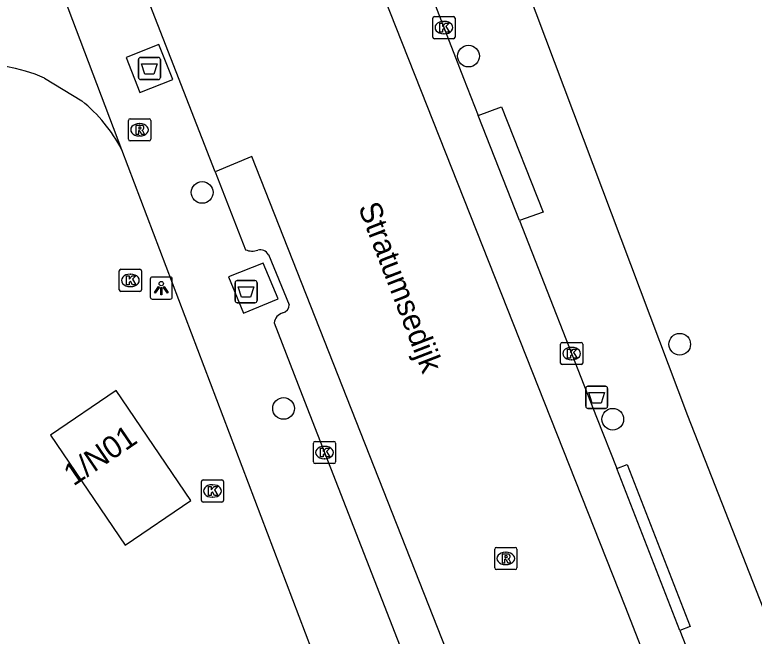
# Model space of a CAD drawing. Extents: x 161087 to 161922, y 382574 to 383873.
# Drawn here: x 161740.93 to 161774.27, y 382676.22 to 382704.24 of the extents above; entities that cross this region are included whole.
import ezdxf

# ---------------------------------------------------------------- set-up
doc = ezdxf.new("R2010")
doc.units = 0
for name, color, linetype in [('IMGEO_Afval_apart_plaats', 7, 'Continuous'), ('IMGEO_Afvalbak', 7, 'Continuous'), ('IMGEO_Boom', 7, 'Continuous'), ('IMGEO_Kolk', 7, 'Continuous'), ('IMGEO_Lichtpunt', 7, 'Continuous'), ('IMGEO_Openbare_ruimte_label', 7, 'Continuous'), ('IMGEO_Pand', 7, 'Continuous'), ('IMGEO_Pand_nummerreeks', 7, 'Continuous'), ('IMGEO_Rijbaan_lokaal_open', 7, 'Continuous'), ('IMGEO_Rioolput', 7, 'Continuous'), ('IMGEO_Voetpad_gesloten', 7, 'Continuous'), ('IMGEO_Voetpad_open', 7, 'Continuous')]:
    doc.layers.add(name, color=color, linetype=linetype)

msp = doc.modelspace()

# ---------------------------------------------------------------- linework, layer by layer
at = {"layer": 'IMGEO_Afval_apart_plaats'}
for p, q in [((161746.509, 382701.417), (161746.509, 382702.217)), ((161746.509, 382702.217), (161746.509, 382701.417)), ((161746.609, 382702.317), (161747.399, 382702.317)), ((161747.399, 382702.317), (161746.609, 382702.317)), ((161747.499, 382702.217), (161747.499, 382701.417)), ((161747.499, 382701.417), (161747.499, 382702.217)), ((161747.399, 382701.317), (161746.609, 382701.317)), ((161746.609, 382701.317), (161747.399, 382701.317)), ((161750.867, 382691.355), (161750.867, 382692.155)), ((161750.867, 382692.155), (161750.867, 382691.355)), ((161750.967, 382692.255), (161751.757, 382692.255)), ((161751.757, 382692.255), (161750.967, 382692.255)), ((161751.857, 382692.155), (161751.857, 382691.355)), ((161751.857, 382691.355), (161751.857, 382692.155)), ((161751.757, 382691.255), (161750.967, 382691.255)), ((161750.967, 382691.255), (161751.757, 382691.255))]:
    msp.add_line(p, q, dxfattribs=at)
for points in [[(161746.652, 382702.031), (161747.356, 382702.031), (161747.207, 382701.561), (161746.801, 382701.561), (161746.652, 382702.031)], [(161751.01, 382691.969), (161751.714, 382691.969), (161751.565, 382691.499), (161751.159, 382691.499), (161751.01, 382691.969)]]:
    msp.add_lwpolyline(points, dxfattribs=at)
for centre, start, end in [((161746.609, 382702.217), 90, 180), ((161746.609, 382702.217), 90, 180), ((161747.399, 382702.217), 0, 90), ((161747.399, 382702.217), 360, 90), ((161746.609, 382701.417), 180, 270), ((161746.609, 382701.417), 180, 270), ((161747.399, 382701.417), 270, 0), ((161747.399, 382701.417), 270, 0), ((161750.967, 382692.155), 90, 180), ((161750.967, 382692.155), 90, 180), ((161751.757, 382692.155), 0, 90), ((161751.757, 382692.155), 360, 90), ((161750.967, 382691.355), 180, 270), ((161750.967, 382691.355), 180, 270), ((161751.757, 382691.355), 270, 0), ((161751.757, 382691.355), 270, 0)]:
    msp.add_arc(centre, 0.1, start, end, dxfattribs=at)
at = {"layer": 'IMGEO_Afvalbak'}
for p, q in [((161766.676, 382686.587), (161766.676, 382687.387)), ((161766.676, 382687.387), (161766.676, 382686.587)), ((161766.776, 382687.487), (161767.566, 382687.487)), ((161767.566, 382687.487), (161766.776, 382687.487)), ((161767.666, 382687.387), (161767.666, 382686.587)), ((161767.666, 382686.587), (161767.666, 382687.387)), ((161767.566, 382686.487), (161766.776, 382686.487)), ((161766.776, 382686.487), (161767.566, 382686.487))]:
    msp.add_line(p, q, dxfattribs=at)
msp.add_lwpolyline([(161766.819, 382687.201), (161767.523, 382687.201), (161767.374, 382686.731), (161766.968, 382686.731), (161766.819, 382687.201)], dxfattribs=at)
for centre, start, end in [((161766.776, 382687.387), 90, 180), ((161766.776, 382687.387), 90, 180), ((161767.566, 382687.387), 0, 90), ((161767.566, 382687.387), 360, 90), ((161766.776, 382686.587), 180, 270), ((161766.776, 382686.587), 180, 270), ((161767.566, 382686.587), 270, 0), ((161767.566, 382686.587), 270, 0)]:
    msp.add_arc(centre, 0.1, start, end, dxfattribs=at)
at = {"layer": 'IMGEO_Boom'}
for centre in [(161761.392, 382702.376), (161749.383, 382696.228), (161770.915, 382689.383), (161753.053, 382686.487), (161767.897, 382686)]:
    msp.add_circle(centre, 0.489, dxfattribs=at)
at = {"layer": 'IMGEO_Kolk'}
for p, q in [((161759.783, 382703.234), (161759.783, 382704.086)), ((161759.858, 382704.16), (161760.71, 382704.16)), ((161760.784, 382704.086), (161760.784, 382703.234)), ((161760.271, 382703.94), (161760.296, 382703.94)), ((161760.294, 382703.38), (161760.269, 382703.38)), ((161760.71, 382703.16), (161759.858, 382703.16)), ((161745.647, 382691.837), (161745.647, 382692.689)), ((161745.722, 382692.763), (161746.574, 382692.763)), ((161746.648, 382692.689), (161746.648, 382691.837)), ((161746.135, 382692.543), (161746.16, 382692.543)), ((161746.574, 382691.763), (161745.722, 382691.763)), ((161746.158, 382691.983), (161746.133, 382691.983)), ((161765.541, 382688.536), (161765.541, 382689.388)), ((161765.616, 382689.462), (161766.468, 382689.462)), ((161766.542, 382689.388), (161766.542, 382688.536)), ((161766.029, 382689.242), (161766.054, 382689.242)), ((161766.468, 382688.462), (161765.616, 382688.462)), ((161766.052, 382688.682), (161766.027, 382688.682)), ((161754.397, 382684.073), (161754.397, 382684.925)), ((161754.472, 382684.999), (161755.324, 382684.999)), ((161754.885, 382684.779), (161754.91, 382684.779)), ((161755.398, 382684.925), (161755.398, 382684.073)), ((161754.908, 382684.219), (161754.883, 382684.219)), ((161755.324, 382683.999), (161754.472, 382683.999)), ((161749.348, 382682.339), (161749.348, 382683.191)), ((161749.423, 382683.265), (161750.275, 382683.265)), ((161749.836, 382683.045), (161749.861, 382683.045)), ((161750.349, 382683.191), (161750.349, 382682.339)), ((161749.859, 382682.485), (161749.834, 382682.485)), ((161750.275, 382682.265), (161749.423, 382682.265))]:
    msp.add_line(p, q, dxfattribs=at)
for points in [[(161759.783, 382703.234), (161759.783, 382704.086)], [(161759.858, 382704.16), (161760.71, 382704.16)], [(161760.784, 382704.086), (161760.784, 382703.234)], [(161760.104, 382703.86), (161760.227, 382703.86), (161760.227, 382703.709), (161760.357, 382703.86), (161760.521, 382703.86), (161760.375, 382703.709), (161760.528, 382703.46), (161760.376, 382703.46), (161760.291, 382703.624), (161760.227, 382703.557), (161760.227, 382703.46), (161760.104, 382703.46), (161760.104, 382703.86)], [(161760.71, 382703.16), (161759.858, 382703.16)], [(161745.647, 382691.837), (161745.647, 382692.689)], [(161745.722, 382692.763), (161746.574, 382692.763)], [(161746.648, 382692.689), (161746.648, 382691.837)], [(161745.968, 382692.463), (161746.091, 382692.463), (161746.091, 382692.312), (161746.221, 382692.463), (161746.385, 382692.463), (161746.239, 382692.312), (161746.392, 382692.063), (161746.24, 382692.063), (161746.155, 382692.227), (161746.091, 382692.16), (161746.091, 382692.063), (161745.968, 382692.063), (161745.968, 382692.463)], [(161746.574, 382691.763), (161745.722, 382691.763)], [(161765.541, 382688.536), (161765.541, 382689.388)], [(161765.616, 382689.462), (161766.468, 382689.462)], [(161766.542, 382689.388), (161766.542, 382688.536)], [(161765.862, 382689.162), (161765.985, 382689.162), (161765.985, 382689.011), (161766.115, 382689.162), (161766.279, 382689.162), (161766.133, 382689.011), (161766.286, 382688.762), (161766.134, 382688.762), (161766.049, 382688.926), (161765.985, 382688.859), (161765.985, 382688.762), (161765.862, 382688.762), (161765.862, 382689.162)], [(161766.468, 382688.462), (161765.616, 382688.462)], [(161754.397, 382684.073), (161754.397, 382684.925)], [(161754.472, 382684.999), (161755.324, 382684.999)], [(161754.718, 382684.699), (161754.841, 382684.699), (161754.841, 382684.548), (161754.971, 382684.699), (161755.135, 382684.699), (161754.989, 382684.548), (161755.142, 382684.299), (161754.99, 382684.299), (161754.905, 382684.463), (161754.841, 382684.396), (161754.841, 382684.299), (161754.718, 382684.299), (161754.718, 382684.699)], [(161755.398, 382684.925), (161755.398, 382684.073)], [(161755.324, 382683.999), (161754.472, 382683.999)], [(161749.348, 382682.339), (161749.348, 382683.191)], [(161749.423, 382683.265), (161750.275, 382683.265)], [(161750.349, 382683.191), (161750.349, 382682.339)], [(161749.669, 382682.965), (161749.792, 382682.965), (161749.792, 382682.814), (161749.922, 382682.965), (161750.086, 382682.965), (161749.94, 382682.814), (161750.093, 382682.565), (161749.941, 382682.565), (161749.856, 382682.729), (161749.792, 382682.662), (161749.792, 382682.565), (161749.669, 382682.565), (161749.669, 382682.965)], [(161750.275, 382682.265), (161749.423, 382682.265)]]:
    msp.add_lwpolyline(points, dxfattribs=at)
for centre, start, end in [((161759.86, 382704.084), 91.552, 178.448), ((161759.86, 382704.084), 91.552, 178.448), ((161760.708, 382704.084), 1.552, 88.448), ((161760.708, 382704.084), 1.552, 88.448), ((161759.86, 382703.236), 181.552, 268.448), ((161759.86, 382703.236), 181.552, 268.448), ((161760.708, 382703.236), 271.552, 358.448), ((161760.708, 382703.236), 271.552, 358.448), ((161745.724, 382692.687), 91.552, 178.448), ((161745.724, 382692.687), 91.552, 178.448), ((161746.572, 382692.687), 1.552, 88.448), ((161746.572, 382692.687), 1.552, 88.448), ((161745.724, 382691.839), 181.552, 268.448), ((161745.724, 382691.839), 181.552, 268.448), ((161746.572, 382691.839), 271.552, 358.448), ((161746.572, 382691.839), 271.552, 358.448), ((161765.618, 382689.386), 91.552, 178.448), ((161765.618, 382689.386), 91.552, 178.448), ((161766.466, 382689.386), 1.552, 88.448), ((161766.466, 382689.386), 1.552, 88.448), ((161765.618, 382688.538), 181.552, 268.448), ((161765.618, 382688.538), 181.552, 268.448), ((161766.466, 382688.538), 271.552, 358.448), ((161766.466, 382688.538), 271.552, 358.448), ((161754.474, 382684.923), 91.552, 178.448), ((161754.474, 382684.923), 91.552, 178.448), ((161755.322, 382684.923), 1.552, 88.448), ((161755.322, 382684.923), 1.552, 88.448), ((161754.474, 382684.075), 181.552, 268.448), ((161754.474, 382684.075), 181.552, 268.448), ((161755.322, 382684.075), 271.552, 358.448), ((161755.322, 382684.075), 271.552, 358.448), ((161749.425, 382683.189), 91.552, 178.448), ((161749.425, 382683.189), 91.552, 178.448), ((161750.273, 382683.189), 1.552, 88.448), ((161750.273, 382683.189), 1.552, 88.448), ((161749.425, 382682.341), 181.552, 268.448), ((161749.425, 382682.341), 181.552, 268.448), ((161750.273, 382682.341), 271.552, 358.448), ((161750.273, 382682.341), 271.552, 358.448)]:
    msp.add_arc(centre, 0.0765, start, end, dxfattribs=at)
for centre, major_axis, ratio, start_param, end_param in [((161760.27, 382703.66), (-0.387, 0.002), 0.722429, 4.712389, 7.853982), ((161760.295, 382703.66), (-0.39, 0.002), 0.717154, 1.570796, 4.712389), ((161746.134, 382692.263), (-0.387, 0.002), 0.722429, 4.712389, 7.853982), ((161746.159, 382692.263), (-0.39, 0.002), 0.717154, 1.570796, 4.712389), ((161766.028, 382688.962), (-0.387, 0.002), 0.722429, 4.712389, 7.853982), ((161766.053, 382688.962), (-0.39, 0.002), 0.717154, 1.570796, 4.712389), ((161754.884, 382684.499), (-0.387, 0.002), 0.722429, 4.712389, 7.853982), ((161754.909, 382684.499), (-0.39, 0.002), 0.717154, 1.570796, 4.712389), ((161749.835, 382682.765), (-0.387, 0.002), 0.722429, 4.712389, 7.853982), ((161749.86, 382682.765), (-0.39, 0.002), 0.717154, 1.570796, 4.712389)]:
    msp.add_ellipse(centre, major_axis=major_axis, ratio=ratio, start_param=start_param, end_param=end_param, dxfattribs=at)
at = {"layer": 'IMGEO_Lichtpunt'}
for p, q in [((161747.943, 382692.414), (161747.135, 382692.414)), ((161747.943, 382692.414), (161747.135, 382692.414)), ((161747.041, 382692.319), (161747.041, 382691.512)), ((161747.041, 382692.319), (161747.041, 382691.512)), ((161748.037, 382691.512), (161748.037, 382692.319)), ((161748.037, 382691.512), (161748.037, 382692.319)), ((161747.135, 382691.418), (161747.943, 382691.418)), ((161747.135, 382691.418), (161747.943, 382691.418))]:
    msp.add_line(p, q, dxfattribs=at)
for points in [[(161747.415, 382691.983), (161747.454, 382691.955), (161747.266, 382691.693), (161747.228, 382691.72), (161747.415, 382691.983)], [(161747.517, 382691.935), (161747.564, 382691.935), (161747.564, 382691.613), (161747.517, 382691.613), (161747.517, 382691.935)], [(161747.627, 382691.955), (161747.665, 382691.982), (161747.852, 382691.72), (161747.813, 382691.692), (161747.627, 382691.955)]]:
    msp.add_lwpolyline(points, dxfattribs=at)
msp.add_circle((161747.54, 382692.117), 0.0994, dxfattribs=at)
for centre, start, end in [((161747.135, 382692.319), 90, 180), ((161747.135, 382692.319), 90, 180), ((161747.943, 382692.319), 0, 90), ((161747.943, 382692.319), 0, 90), ((161747.135, 382691.512), 180, 270), ((161747.135, 382691.512), 180, 270), ((161747.943, 382691.512), 270, 0), ((161747.943, 382691.512), 270, 360)]:
    msp.add_arc(centre, 0.0946, start, end, dxfattribs=at)
at = {"layer": 'IMGEO_Pand'}
msp.add_lwpolyline([(161742.539, 382685.277), (161745.911, 382680.323), (161748.877, 382682.342), (161745.503, 382687.294), (161742.539, 382685.277)], dxfattribs=at)
at = {"layer": 'IMGEO_Rijbaan_lokaal_open'}
for points in [[(161742.826, 382742.772), (161754.209, 382713.572), (161768.441, 382677.581), (161785.32, 382634.34), (161787.244, 382635.106)], [(161749.972, 382697.162), (161746.805, 382705.307)], [(161774.224, 382639.932), (161763.88, 382666.739), (161751.621, 382697.849), (161749.972, 382697.162)]]:
    msp.add_lwpolyline(points, dxfattribs=at)
at = {"layer": 'IMGEO_Rioolput'}
for p, q in [((161746.06, 382698.627), (161746.06, 382699.479)), ((161746.135, 382699.553), (161746.987, 382699.553)), ((161747.061, 382699.479), (161747.061, 382698.627)), ((161746.548, 382699.333), (161746.573, 382699.333)), ((161746.571, 382698.773), (161746.546, 382698.773)), ((161746.987, 382698.553), (161746.135, 382698.553)), ((161762.572, 382679.297), (161762.572, 382680.149)), ((161762.647, 382680.223), (161763.499, 382680.223)), ((161763.573, 382680.149), (161763.573, 382679.297)), ((161763.06, 382680.003), (161763.085, 382680.003)), ((161763.083, 382679.443), (161763.058, 382679.443)), ((161763.499, 382679.223), (161762.647, 382679.223))]:
    msp.add_line(p, q, dxfattribs=at)
for points in [[(161746.06, 382698.627), (161746.06, 382699.479)], [(161746.135, 382699.553), (161746.987, 382699.553)], [(161747.061, 382699.479), (161747.061, 382698.627)], [(161746.649, 382699.251), (161746.397, 382699.253), (161746.397, 382698.853)], [(161746.575, 382699.172), (161746.521, 382699.172), (161746.521, 382699.091)], [(161746.521, 382699.091), (161746.573, 382699.091)], [(161746.397, 382698.853), (161746.521, 382698.853), (161746.521, 382699.015), (161746.532, 382699.015)], [(161746.579, 382698.986), (161746.65, 382698.853), (161746.79, 382698.853), (161746.725, 382698.979)], [(161746.987, 382698.553), (161746.135, 382698.553)], [(161762.572, 382679.297), (161762.572, 382680.149)], [(161762.647, 382680.223), (161763.499, 382680.223)], [(161763.573, 382680.149), (161763.573, 382679.297)], [(161763.161, 382679.921), (161762.909, 382679.923), (161762.909, 382679.523)], [(161762.909, 382679.523), (161763.033, 382679.523), (161763.033, 382679.685), (161763.044, 382679.685)], [(161763.087, 382679.842), (161763.033, 382679.842), (161763.033, 382679.761)], [(161763.033, 382679.761), (161763.085, 382679.761)], [(161763.091, 382679.656), (161763.162, 382679.523), (161763.302, 382679.523), (161763.237, 382679.649)], [(161763.499, 382679.223), (161762.647, 382679.223)]]:
    msp.add_lwpolyline(points, dxfattribs=at)
for centre, radius, start, end in [((161746.137, 382699.477), 0.0765, 91.552, 178.448), ((161746.137, 382699.477), 0.0765, 91.552, 178.448), ((161746.985, 382699.477), 0.0765, 1.552, 88.448), ((161746.985, 382699.477), 0.0765, 1.552, 88.448), ((161746.557, 382699.28), 0.19, 274.7715, 282.9687), ((161746.581, 382699.076), 0.0964, 77.0061, 93.1865), ((161746.595, 382699.133), 0.0378, 276.6634, 79.6772), ((161746.648, 382699.141), 0.109, 350.3612, 89.416), ((161746.646, 382699.141), 0.112, 277.5842, 350.9817), ((161746.63, 382698.926), 0.108, 29.5134, 73.7905), ((161746.531, 382698.962), 0.0533, 26.0293, 88.6989), ((161746.137, 382698.629), 0.0765, 181.552, 268.448), ((161746.137, 382698.629), 0.0765, 181.552, 268.448), ((161746.985, 382698.629), 0.0765, 271.552, 358.448), ((161746.985, 382698.629), 0.0765, 271.552, 358.448), ((161762.649, 382680.147), 0.0765, 91.552, 178.448), ((161762.649, 382680.147), 0.0765, 91.552, 178.448), ((161763.497, 382680.147), 0.0765, 1.552, 88.448), ((161763.497, 382680.147), 0.0765, 1.552, 88.448), ((161763.043, 382679.632), 0.0533, 26.0293, 88.6989), ((161763.069, 382679.95), 0.19, 274.7715, 282.9687), ((161763.093, 382679.746), 0.0964, 77.0061, 93.1865), ((161763.107, 382679.803), 0.0378, 276.6634, 79.6772), ((161763.16, 382679.811), 0.109, 350.3612, 89.416), ((161763.158, 382679.811), 0.112, 277.5842, 350.9817), ((161763.142, 382679.596), 0.108, 29.5134, 73.7905), ((161762.649, 382679.299), 0.0765, 181.552, 268.448), ((161762.649, 382679.299), 0.0765, 181.552, 268.448), ((161763.497, 382679.299), 0.0765, 271.552, 358.448), ((161763.497, 382679.299), 0.0765, 271.552, 358.448)]:
    msp.add_arc(centre, radius, start, end, dxfattribs=at)
for centre, major_axis, ratio, start_param, end_param in [((161746.547, 382699.053), (-0.387, 0.002), 0.722429, 4.712389, 7.853982), ((161746.572, 382699.053), (-0.39, 0.002), 0.717154, 1.570796, 4.712389), ((161763.059, 382679.723), (-0.387, 0.002), 0.722429, 4.712389, 7.853982), ((161763.084, 382679.723), (-0.39, 0.002), 0.717154, 1.570796, 4.712389)]:
    msp.add_ellipse(centre, major_axis=major_axis, ratio=ratio, start_param=start_param, end_param=end_param, dxfattribs=at)
at = {"layer": 'IMGEO_Voetpad_gesloten'}
for points in [[(161747.433, 382702.894), (161745.955, 382702.31), (161746.575, 382700.741), (161748.053, 382701.325), (161747.433, 382702.894)], [(161752.806, 382691.425), (161752.136, 382693.041), (161750.574, 382692.422), (161751.253, 382690.782), (161752.806, 382691.425)]]:
    msp.add_lwpolyline(points, dxfattribs=at)
at = {"layer": 'IMGEO_Voetpad_open'}
for points in [[(161749.294, 382732.127), (161750.176, 382729.847), (161755.146, 382716.973), (161758.324, 382708.735), (161759.331, 382706.124), (161761.163, 382701.376), (161761.824, 382699.694)], [(161775.138, 382676.312), (161771.278, 382686.152), (161761.433, 382712.304)], [(161741.655, 382708.971), (161745.752, 382698.169)], [(161742.279, 382701.385), (161743.962, 382700.359)], [(161761.824, 382699.694), (161762.883, 382700.082), (161764.753, 382695.333), (161763.685, 382694.956)], [(161763.685, 382694.956), (161761.824, 382699.694)], [(161745.752, 382698.169), (161759.169, 382662.845), (161759.351, 382662.367), (161760.61, 382659.053), (161760.971, 382658.101)], [(161749.972, 382697.162), (161751.34, 382693.644)], [(161763.685, 382694.956), (161767.169, 382686.089), (161768.074, 382683.775)], [(161752.37, 382693.422), (161753.305, 382691.165)], [(161752.623, 382690.345), (161753.892, 382687.082), (161762.703, 382664.502), (161762.855, 382664.109), (161764.649, 382659.466), (161767.914, 382651.017), (161768.786, 382648.771)], [(161768.074, 382683.775), (161768.54, 382683.955), (161771.394, 382676.655), (161770.928, 382676.475)], [(161770.928, 382676.475), (161768.074, 382683.775)], [(161770.928, 382676.475), (161773.946, 382668.758), (161774.899, 382666.339)]]:
    msp.add_lwpolyline(points, dxfattribs=at)
for centre, radius, start, end in [((161739.14, 382694.004), 8.021, 66.9607, 118.9724), ((161739.409, 382694.811), 7.177, 27.8962, 50.6256), ((161751.633, 382694.305), 0.723, 246.0583, 291.0413), ((161751.992, 382693.206), 0.435, 29.7115, 103.1685), ((161752.924, 382691.162), 0.381, 283.79, 0.4813), ((161753.166, 382690.264), 0.549, 105.9989, 171.5023)]:
    msp.add_arc(centre, radius, start, end, dxfattribs=at)

# ---------------------------------------------------------------- texts
at = {"layer": 'IMGEO_Openbare_ruimte_label'}
msp.add_text('Stratumsedijk', height=1, rotation=291.1733, dxfattribs=at).set_placement((161756.406, 382695.562))
at = {"layer": 'IMGEO_Pand_nummerreeks'}
msp.add_text('1/N01', height=1, rotation=34.2342, dxfattribs=at).set_placement((161743.581, 382682.962))

doc.saveas('drawing.dxf')
